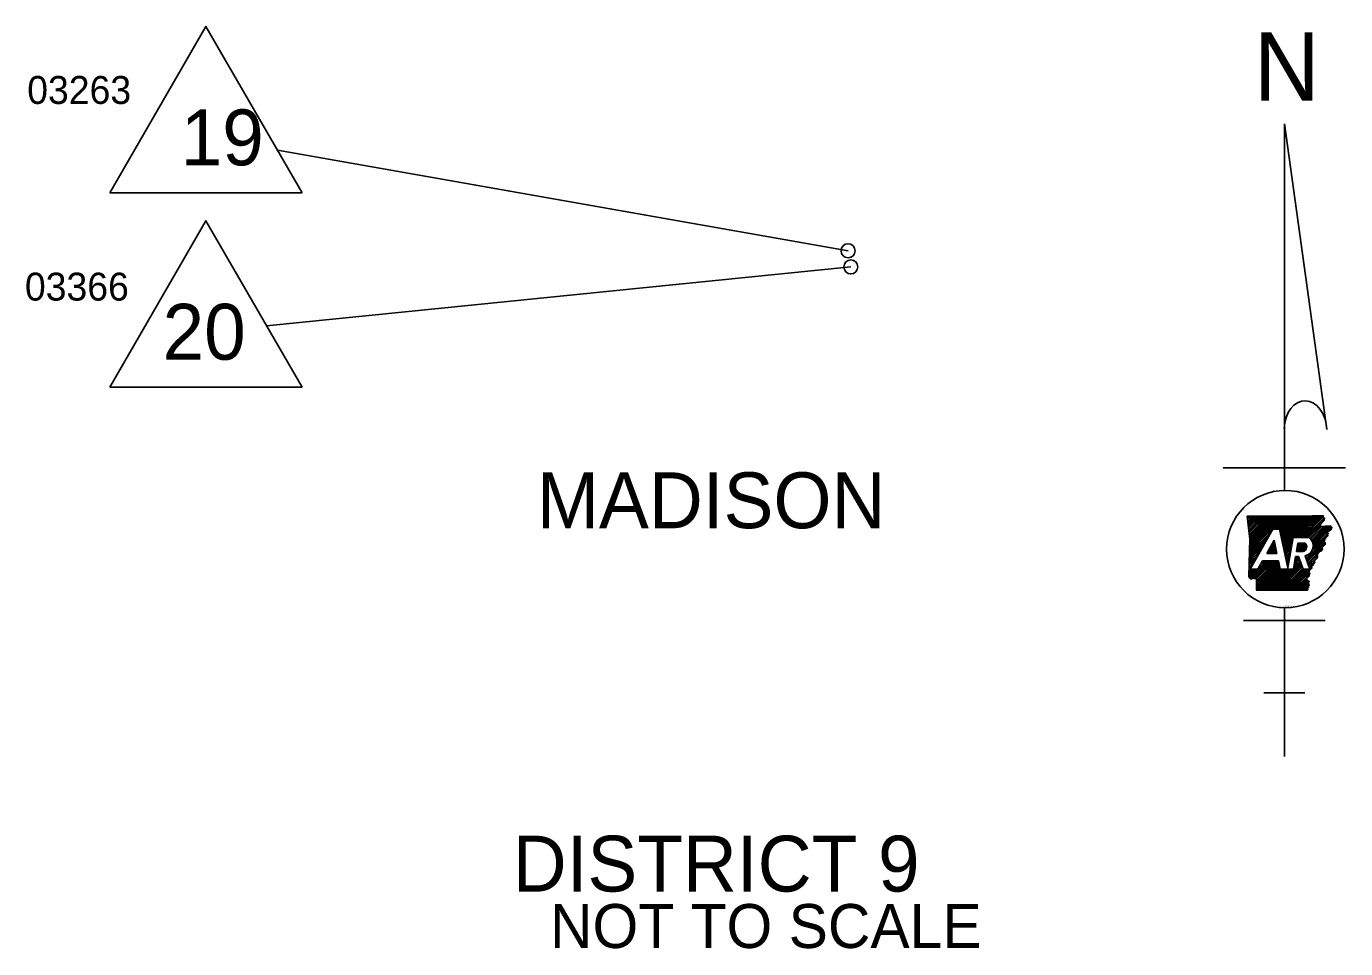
# Model space of a CAD drawing. Extents: x -24122 to 24238, y -8840 to 11381.
# Drawn here: x 11486 to 17152, y -2987 to 976 of the extents above; entities that cross this region are included whole.
import ezdxf

# ---------------------------------------------------------------- set-up
doc = ezdxf.new("R2010")
doc.units = 0
for name, color, linetype in [('R_Annotation', 7, 'Continuous'), ('R_Border', 7, 'Continuous'), ('R_No Plot', 7, 'Continuous')]:
    doc.layers.add(name, color=color, linetype=linetype)

msp = doc.modelspace()

# ---------------------------------------------------------------- linework, layer by layer
at = {"layer": 'R_Annotation'}
for p, q in [((16888.7, 557.8), (17070.5, -756.3)), ((16888.7, -1018.1), (16888.7, 557.8)), ((15014.9, 12.1), (12564.2, 445)), ((11844.1, 260.6), (12670.7, 260.6)), ((15026.9, -57.3), (12517.8, -310)), ((11844.1, -574.8), (12670.7, -574.8)), ((16625.5, -920.6), (17151.8, -920.6)), ((16729, -1131), (16731.2, -1128.8)), ((16729.8, -1137.1), (16738.1, -1128.8)), ((16730.6, -1143.3), (16745.1, -1128.8)), ((16731.3, -1149.5), (16752.1, -1128.8)), ((16732.1, -1155.7), (16759, -1128.8)), ((16732.9, -1161.9), (16766, -1128.8)), ((16733.6, -1168.1), (16773, -1128.8)), ((16734.4, -1174.3), (16779.9, -1128.8)), ((16735.2, -1180.5), (16786.9, -1128.8)), ((16736, -1186.7), (16793.8, -1128.8)), ((16736.7, -1192.9), (16800.8, -1128.8)), ((16737.5, -1199.1), (16807.8, -1128.8)), ((16738.3, -1205.3), (16814.7, -1128.8)), ((16739, -1211.5), (16821.7, -1128.8)), ((16739.3, -1280.9), (16891.5, -1128.7)), ((16739.5, -1273.7), (16884.5, -1128.7)), ((16739.7, -1266.5), (16877.5, -1128.7)), ((16739.8, -1217.7), (16828.7, -1128.8)), ((16740, -1259.3), (16870.5, -1128.7)), ((16740.2, -1252.1), (16863.6, -1128.8)), ((16740.5, -1244.9), (16856.6, -1128.8)), ((16740.6, -1223.9), (16835.6, -1128.8)), ((16740.7, -1237.7), (16849.6, -1128.8)), ((16740.9, -1230.5), (16842.6, -1128.8)), ((16842.7, -1184.4), (16898.5, -1128.7)), ((16849.7, -1184.4), (16905.4, -1128.7)), ((16856.6, -1184.4), (16912.5, -1128.6)), ((16863.6, -1184.4), (16919.5, -1128.5)), ((16867.9, -1187.1), (16926.6, -1128.4)), ((16869.2, -1192.8), (16933.7, -1128.3)), ((16870.4, -1198.5), (16940.8, -1128.2)), ((16871.6, -1204.3), (16947.8, -1128.1)), ((16872.9, -1210), (16954.9, -1128)), ((16874.1, -1215.7), (16962, -1127.8)), ((16875.3, -1221.5), (16969.1, -1127.7)), ((16876.5, -1227.2), (16976.1, -1127.6)), ((16877.8, -1233), (16983.2, -1127.5)), ((16879, -1238.7), (16990.3, -1127.4)), ((16880.2, -1244.4), (16997.4, -1127.3)), ((16881.5, -1250.2), (17004.4, -1127.2)), ((16882.7, -1255.9), (17011.5, -1127)), ((16883.9, -1261.6), (17018.7, -1126.9)), ((16932.3, -1220.2), (17025.8, -1126.7)), ((16939.3, -1220.2), (17032.9, -1126.6)), ((16946.2, -1220.2), (17040.1, -1126.4)), ((16953.2, -1220.2), (17047.2, -1126.2)), ((16960.2, -1220.2), (17054.3, -1126.1)), ((16967.1, -1220.2), (17055.9, -1131.5)), ((16741.3, -1356), (16838.5, -1184.4)), ((16838.5, -1184.4), (16867.4, -1184.4)), ((16974.1, -1220.2), (17059.3, -1135.1)), ((16981.1, -1220.2), (17060.2, -1141.1)), ((16988, -1220.2), (17044.2, -1164)), ((16994.4, -1220.9), (17042.9, -1172.3)), ((16998.2, -1224), (17050.2, -1172)), ((17001.6, -1227.6), (17057.6, -1171.6)), ((17004.6, -1231.5), (17064.9, -1171.2)), ((17007.2, -1235.9), (17072.2, -1170.8)), ((17009.3, -1240.8), (17079.6, -1170.5)), ((17010.9, -1246.1), (17086.2, -1170.8)), ((17011.8, -1252.1), (17089.5, -1174.5)), ((17086.4, -1184.6), (17092.7, -1178.2)), ((16738.3, -1309.7), (16805.7, -1242.3)), ((16738.6, -1302.5), (16814.8, -1226.2)), ((16738.8, -1295.3), (16823.9, -1210.2)), ((16739, -1288.1), (16833, -1194.1)), ((16812.8, -1288.7), (16844.6, -1232.5)), ((16830.6, -1257.3), (16846.5, -1241.4)), ((16839.7, -1241.3), (16845.3, -1235.7)), ((16885.1, -1267.4), (16924.7, -1227.9)), ((16886.4, -1273.1), (16923.2, -1236.3)), ((16887.6, -1278.9), (16921.7, -1244.7)), ((16926, -1220.2), (16993.5, -1220.2)), ((16940.7, -1281.1), (16977.3, -1244.4)), ((16942.1, -1272.7), (16970.4, -1244.4)), ((16943.6, -1264.3), (16963.4, -1244.4)), ((16945, -1255.8), (16956.4, -1244.4)), ((16946.5, -1247.4), (16949.5, -1244.4)), ((16947, -1244.4), (16978.7, -1244.4)), ((16981.7, -1310.2), (17058.9, -1233)), ((16983.5, -1315.3), (17060.2, -1238.6)), ((16985.4, -1320.4), (17061.5, -1244.3)), ((17004.4, -1280.5), (17057.6, -1227.3)), ((17010.4, -1267.5), (17073.6, -1204.3)), ((17011.9, -1259.1), (17072.8, -1198.1)), ((17065.8, -1219), (17074.4, -1210.4)), ((16737.6, -1331.3), (16778.5, -1290.5)), ((16737.8, -1324.1), (16787.6, -1274.4)), ((16738.1, -1316.9), (16796.7, -1258.3)), ((16812.8, -1288.7), (16856.6, -1288.7)), ((16813.2, -1288.7), (16849, -1252.9)), ((16820.1, -1288.7), (16850.2, -1258.6)), ((16821.5, -1273.4), (16847.7, -1247.1)), ((16827.1, -1288.7), (16851.4, -1264.4)), ((16834.1, -1288.7), (16852.6, -1270.1)), ((16841, -1288.7), (16853.9, -1275.8)), ((16848, -1288.7), (16855.1, -1281.6)), ((16855, -1288.7), (16856.3, -1287.3)), ((16888.8, -1284.6), (16920.3, -1253.2)), ((16890.1, -1290.3), (16918.8, -1261.6)), ((16891.3, -1296.1), (16917.3, -1270)), ((16892.5, -1301.8), (16915.8, -1278.5)), ((16893.7, -1307.5), (16914.4, -1286.9)), ((16895, -1313.3), (16912.9, -1295.3)), ((16934.7, -1315.4), (16948.6, -1301.5)), ((16936.1, -1306.9), (16941.6, -1301.5)), ((16948.8, -1301.5), (16937.1, -1301.5)), ((16940.6, -1281.1), (16969.6, -1281.1)), ((16947.6, -1281.1), (16981.2, -1247.5)), ((16969, -1356), (16948.8, -1301.5)), ((16954.6, -1281.1), (16983.6, -1252.2)), ((16961.6, -1281.1), (16984.8, -1257.8)), ((16968.5, -1281.1), (16984.3, -1265.4)), ((16977.4, -1298.5), (16998.6, -1356)), ((16977.9, -1300), (16980, -1297.9)), ((16979.8, -1305.1), (16993, -1291.8)), ((16987.3, -1325.4), (17062.8, -1250)), ((16989.2, -1330.5), (17031, -1288.7)), ((16991, -1335.6), (17030.2, -1296.5)), ((17039, -1280.7), (17048.7, -1271)), ((16735.8, -1388.9), (16768.6, -1356)), ((16735.9, -1381.8), (16761.7, -1356)), ((16736.2, -1374.6), (16754.7, -1356)), ((16736.4, -1367.4), (16747.7, -1356)), ((16736.6, -1360.2), (16742.1, -1354.7)), ((16736.9, -1352.9), (16751.2, -1338.6)), ((16737.1, -1345.7), (16760.3, -1322.6)), ((16737.4, -1338.5), (16769.4, -1306.5)), ((16738.4, -1393.2), (16811.6, -1320)), ((16774.7, -1356), (16741.3, -1356)), ((16742.5, -1396.1), (16818.6, -1320)), ((16747.5, -1398), (16825.5, -1320)), ((16755.8, -1396.7), (16832.5, -1320)), ((16762.9, -1396.6), (16839.5, -1320)), ((16768.3, -1398.1), (16846.4, -1320)), ((16768.6, -1411.8), (16860.4, -1320)), ((16768.6, -1404.8), (16853.4, -1320)), ((16768.6, -1418.7), (16864, -1323.3)), ((16768.6, -1425.7), (16865.3, -1329.1)), ((16768.6, -1432.6), (16866.5, -1334.8)), ((16768.7, -1439.6), (16867.7, -1340.5)), ((16768.8, -1446.4), (16868.9, -1346.3)), ((16795.1, -1320), (16774.7, -1356)), ((16775.7, -1446.4), (16870.2, -1352)), ((16782.6, -1342.1), (16804.6, -1320)), ((16782.7, -1446.5), (16873.1, -1356)), ((16789.6, -1446.5), (16880.1, -1356)), ((16791.7, -1326), (16797.7, -1320)), ((16863.3, -1320), (16795.1, -1320)), ((16796.6, -1446.5), (16887, -1356)), ((16803.5, -1446.5), (16894, -1356)), ((16810.5, -1446.5), (16901, -1356)), ((16817.5, -1446.5), (16907.9, -1356)), ((16824.4, -1446.5), (16914.9, -1356)), ((16831.4, -1446.5), (16921.9, -1356)), ((16838.3, -1446.5), (16958.1, -1326.7)), ((16845.3, -1446.6), (16960, -1331.8)), ((16852.2, -1446.6), (16961.9, -1336.9)), ((16859.2, -1446.6), (16963.8, -1342)), ((16866.1, -1446.6), (16965.6, -1347.1)), ((16927.6, -1356), (16871, -1356)), ((16873.1, -1446.6), (16967.5, -1352.2)), ((16880, -1446.6), (16970.6, -1356)), ((16887, -1446.6), (16977.6, -1356)), ((16894, -1446.6), (16984.6, -1356)), ((16896.2, -1319), (16911.4, -1303.8)), ((16897.4, -1324.8), (16910, -1312.2)), ((16898.6, -1330.5), (16908.5, -1320.7)), ((16899.9, -1336.2), (16907, -1329.1)), ((16900.9, -1446.7), (16991.5, -1356)), ((16901.1, -1342), (16905.6, -1337.5)), ((16902.3, -1347.7), (16904.1, -1346)), ((16928.8, -1349.1), (16956.3, -1321.7)), ((16930.3, -1340.7), (16954.4, -1316.6)), ((16931.7, -1332.2), (16952.5, -1311.5)), ((16933.2, -1323.8), (16950.6, -1306.4)), ((16998.6, -1356), (16969, -1356)), ((16992.9, -1340.7), (17029.4, -1304.2)), ((16994.8, -1345.8), (17016.2, -1324.4)), ((16996.7, -1350.9), (17013.2, -1334.4)), ((16907.9, -1446.7), (16993.9, -1360.7)), ((16914.8, -1446.7), (16994.2, -1367.3)), ((16921.8, -1446.7), (16994.5, -1374)), ((16928.7, -1446.7), (16994.8, -1380.6)), ((16935.7, -1446.7), (16983.4, -1399)), ((16942.6, -1446.7), (16985.5, -1403.8)), ((16949.6, -1446.7), (16987.7, -1408.7)), ((16956.5, -1446.7), (16989.8, -1413.5)), ((16963.5, -1446.8), (16992, -1418.3)), ((16970.5, -1446.8), (16993.8, -1423.5)), ((16977.4, -1446.8), (16990.6, -1433.6)), ((16984.4, -1446.8), (16987.5, -1443.7)), ((16888.7, -2161.8), (16888.7, -1522.2)), ((16713.2, -1576.5), (17064.1, -1576.5)), ((16800.9, -1888.1), (16976.4, -1888.1))]:
    msp.add_line(p, q, dxfattribs=at)
for points in [[(12670.7, 260.6), (12257.4, 976.4), (11844.1, 260.6)], [(12670.7, -574.8), (12257.4, 141), (11844.1, -574.8)], [(16728.7, -1128.8), (16824.8, -1128.8), (16909.2, -1128.7), (17008.7, -1127.1), (17054.8, -1126)], [(16728.7, -1128.8), (16824.8, -1128.8), (16909.2, -1128.7), (17008.7, -1127.1), (17054.8, -1126)], [(16739.4, -1278.2), (16741, -1227.5), (16728.7, -1128.8)], [(16735.7, -1388.8), (16741, -1227.6), (16728.7, -1128.8)], [(16867.4, -1184.4), (16903.1, -1351.4), (16926, -1220.2)], [(17085, -1170.2), (17093.3, -1178.9), (17072.6, -1195.9), (17074.8, -1213.1), (17057, -1224.9), (17063.1, -1251.3), (17049.4, -1263.8), (17048.2, -1277.4), (17031.5, -1283.4), (17028.9, -1309.1), (17016.9, -1321.9), (17011.1, -1341.2), (16993.7, -1357.2), (16995, -1385.3), (16983.2, -1398.6), (16994, -1422.8), (16986.5, -1446.8)], [(17040.5, -1172.5), (17085.6, -1170.1)], [(17040.5, -1172.4), (17085.6, -1170.2)], [(16844.6, -1232.5), (16856.6, -1288.7)], [(16940.6, -1281.1), (16947, -1244.4)], [(16735.7, -1388.8), (16739.4, -1278.2)], [(16937.1, -1301.5), (16927.6, -1356)], [(16871, -1356), (16863.3, -1320)], [(16986.5, -1446.8), (16768.7, -1446.4), (16768.6, -1398.3)], [(16986.5, -1446.8), (16768.7, -1446.4), (16768.6, -1398.4)]]:
    msp.add_lwpolyline(points, dxfattribs=at)
for centre in [(15014.9, 12.1), (15026.9, -57.3)]:
    msp.add_circle(centre, 30.2, dxfattribs=at)
for centre, major_axis, ratio, start_param, end_param in [((16979.5, -759.2), (-3.9, 126.3), 0.719778, 4.712385, 7.768526), ((16962.6, -1259.9), (-22.3, 0), 0.999987, 1.887169, 3.90762), ((16968.4, -1255.9), (-43.6, 0), 0.999987, 1.777838, 4.099264)]:
    msp.add_ellipse(centre, major_axis=major_axis, ratio=ratio, start_param=start_param, end_param=end_param, dxfattribs=at)
msp.add_ellipse((16892.8, -1270.1), major_axis=(252.1, 0), ratio=0.999976, dxfattribs=at)
for points in [[(17054.8, -1126), (17055.1, -1128.7), (17055.9, -1130), (17056, -1132.5), (17057, -1133.6), (17058.8, -1134.7), (17060.3, -1136.4), (17060.7, -1138.4), (17060.2, -1140.5), (17060.1, -1142.8), (17059.8, -1144.9), (17059.4, -1146.7), (17058, -1148.2), (17056.7, -1149.2), (17055.4, -1150.4), (17054.5, -1151.8), (17053, -1153.2), (17051.4, -1154.7), (17050.2, -1156), (17048.9, -1157.7), (17048.3, -1159.5), (17047, -1160.8), (17045.9, -1162), (17044.5, -1163.6), (17043.8, -1165.2), (17042.4, -1167), (17042.1, -1168.8), (17041.2, -1170.2), (17041.2, -1170.5)], [(17054.8, -1126), (17055.1, -1128.7), (17055.9, -1130), (17056, -1132.5), (17057, -1133.6), (17058.8, -1134.7), (17060.3, -1136.4), (17060.7, -1138.4), (17060.2, -1140.5), (17060.1, -1142.8), (17059.8, -1144.8), (17059.5, -1146.7), (17058, -1148.2), (17056.7, -1149.2), (17055.4, -1150.5), (17054.5, -1151.8), (17053, -1153.2), (17051.4, -1154.7), (17050.2, -1156), (17049, -1157.7), (17048.4, -1159.5), (17047, -1160.8), (17045.9, -1162), (17044.5, -1163.6), (17043.8, -1165.2), (17042.4, -1167.1), (17042.1, -1168.8), (17041.2, -1170.3), (17041.2, -1170.5)], [(17085, -1170.2), (17085.6, -1170.2), (17087.6, -1172.3), (17088.5, -1174.1), (17089.9, -1175.1), (17091.3, -1175.6), (17092.5, -1177), (17093.2, -1178.5), (17092.8, -1179.8), (17091.1, -1179.9), (17089.3, -1180.2), (17087.5, -1180.1), (17086.1, -1181.4), (17087.4, -1182.9), (17089.1, -1184.4), (17089.6, -1186), (17088.6, -1187.5), (17086.7, -1188.4), (17084.9, -1189.1), (17083.2, -1190.5), (17082.4, -1191.9), (17080.6, -1192.5), (17078.7, -1193), (17077.1, -1193.2), (17075.2, -1193.6), (17073.3, -1194.5), (17072.6, -1196), (17072.8, -1198.2), (17072.7, -1200.5), (17074.7, -1201.3), (17076.4, -1201.4), (17078.1, -1202.2), (17077.9, -1203.5), (17076.6, -1205.2), (17075.2, -1206.5), (17073.7, -1207.2), (17072.3, -1208.4), (17072.8, -1209.7), (17074, -1210.5), (17074.9, -1211.9), (17074.8, -1213.1), (17073.4, -1214), (17071.8, -1213.6), (17070.7, -1212.1), (17069.4, -1211.7), (17068.2, -1211.2), (17067, -1211.9), (17067, -1213.6), (17066.5, -1215.5), (17066.9, -1216.8), (17067.4, -1218.7), (17067.3, -1220.2), (17066.9, -1222.2), (17065.9, -1224.3), (17064.7, -1224.9), (17064.2, -1222.7), (17064, -1220.8), (17063.2, -1219.8), (17062.3, -1219.7), (17061.1, -1220.6), (17059.7, -1222), (17058, -1223.5), (17057, -1224.9), (17057.5, -1226.8), (17058.8, -1227.2), (17059.8, -1226.9), (17060.4, -1225.7), (17061.3, -1225.6), (17062.3, -1227.4)], [(17062.3, -1227.4), (17062.6, -1229.1), (17061.6, -1230.9), (17061.2, -1232.8), (17061.3, -1234.6), (17059.4, -1235.6), (17057.8, -1236.8), (17058.8, -1238.3), (17060.6, -1239.6), (17062.3, -1240.5), (17063.4, -1241.6), (17063.7, -1244), (17064, -1245.6), (17064.7, -1247.7), (17064.9, -1249.2), (17063.8, -1251), (17062.6, -1251.3), (17061.2, -1250.9), (17059.7, -1250.8), (17058.5, -1251.9), (17057.6, -1253.6), (17056.7, -1255.3), (17056, -1256.7), (17055.3, -1258.3), (17054.1, -1260.1), (17052.5, -1260.3), (17050.6, -1260.8), (17049.4, -1262.1), (17049.6, -1264.3), (17050.7, -1265.8), (17051.5, -1267.6), (17052.1, -1269.3), (17051.8, -1271.3), (17051, -1272.8), (17049.9, -1273.7), (17049.4, -1275.6), (17048.6, -1277), (17047.9, -1277.5), (17046.5, -1277.4), (17045, -1277.1), (17043.7, -1277.2), (17042.4, -1277.8), (17041.2, -1277.4), (17039.9, -1276), (17038.8, -1274.9), (17037.6, -1274.5), (17036.3, -1275.2), (17036.1, -1277.1), (17036.7, -1279.1), (17037.2, -1281.9), (17036.7, -1283.5), (17036.5, -1286.3)], [(17036.5, -1286.3), (17034.5, -1287.9), (17033.5, -1289.5), (17028.2, -1289), (17028.4, -1290.9), (17026.5, -1291.9), (17024.8, -1293.1), (17025.8, -1294.5), (17027.6, -1295.8), (17029.4, -1296.8), (17030.5, -1297.8), (17030.8, -1300.3), (17031.1, -1301.8), (17031.7, -1304), (17031.9, -1305.4), (17030.8, -1307.2), (17029.6, -1307.6), (17028.3, -1307.1), (17026.7, -1307), (17025.5, -1308.2), (17024.6, -1309.9), (17023.7, -1311.6), (17023, -1313), (17022.3, -1314.5), (17021.1, -1316.3), (17019.5, -1316.6), (17017.6, -1317.1), (17016.5, -1318.4), (17016.6, -1320.6), (17017.7, -1322.1), (17018.5, -1323.9), (17019.1, -1325.5), (17018.9, -1327.5), (17018, -1329), (17016.9, -1329.9), (17016.5, -1331.8), (17015.7, -1333.3), (17015, -1333.7), (17013.6, -1333.6), (17012, -1333.3), (17010.7, -1333.4), (17009.5, -1334.1), (17008.2, -1333.6), (17006.9, -1332.2), (17005.8, -1331.2), (17004.6, -1330.7), (17003.4, -1331.4), (17003.2, -1333.4), (17003.8, -1335.4), (17004.3, -1338.1), (17003.8, -1339.8), (17003.6, -1342.5)], [(17003.6, -1342.5), (17003.4, -1342.6), (17002.4, -1344), (17003, -1346.1), (17005.3, -1346.9), (17006.3, -1348.9), (17006.4, -1350.7), (17005.6, -1353.1), (17004.6, -1354.3), (17002.5, -1354.7), (17000.9, -1355), (17000.7, -1357.8), (16999.9, -1359.1), (16998.7, -1359.5), (16996.9, -1358.7), (16995.8, -1358.2), (16994.5, -1357.6), (16992.8, -1356.7), (16991.6, -1356.8), (16991.9, -1359.4), (16992.1, -1359.5), (16993.5, -1361.5), (16994.9, -1363.1), (16995.6, -1364.9)], [(17003.6, -1342.5), (17003.4, -1342.6), (17002.4, -1344), (17003, -1346.1), (17005.3, -1346.9), (17006.3, -1348.9), (17006.4, -1350.7), (17005.6, -1353.1), (17004.6, -1354.3), (17002.5, -1354.7), (17000.9, -1355), (17000.7, -1357.8), (16999.9, -1359.1), (16998.7, -1359.5), (16996.9, -1358.7), (16995.8, -1358.2), (16994.5, -1357.6), (16992.8, -1356.7), (16991.6, -1356.8), (16991.9, -1359.4), (16992.1, -1359.5), (16993.5, -1361.5), (16994.9, -1363.1), (16995.6, -1364.9)], [(16768.6, -1398.3), (16768.8, -1398.5), (16767.7, -1397.7), (16766.1, -1396.9), (16764.4, -1396.8), (16762.2, -1396.5), (16760.3, -1396.4), (16758.5, -1395.1), (16756.5, -1396.4), (16754.2, -1397.4), (16752.9, -1396.2), (16751.2, -1397), (16750, -1396.6), (16747.9, -1398.1), (16745.9, -1397.5), (16744.5, -1397.9), (16742.7, -1397.9), (16742.4, -1395.8), (16740.6, -1395.6), (16739.1, -1394.7), (16738.1, -1392.7), (16737.4, -1391), (16735.7, -1388.8)], [(16768.6, -1398.4), (16768.8, -1398.5), (16767.7, -1397.7), (16766.1, -1396.9), (16764.4, -1396.8), (16762.2, -1396.5), (16760.4, -1396.3), (16758.5, -1395.1), (16756.4, -1396.4), (16754.2, -1397.3), (16752.9, -1396.3), (16751.1, -1397), (16750, -1396.6), (16747.9, -1398.1), (16745.9, -1397.5), (16744.5, -1397.9), (16742.7, -1397.9), (16742.3, -1395.9), (16740.6, -1395.6), (16739.1, -1394.7), (16738.1, -1392.6), (16737.4, -1391), (16735.7, -1388.8)], [(16995.6, -1364.9), (16995, -1366.3), (16994.3, -1368.6), (16994.5, -1370.6), (16995.4, -1372.4), (16996.8, -1373.3), (16998.4, -1374.7), (16998.3, -1376.8), (16997.4, -1377.5), (16995.2, -1377), (16993.7, -1376.3), (16992.3, -1376.7), (16990.5, -1377.6), (16989.1, -1377.8), (16989.2, -1380.7), (16991, -1382.7), (16992.6, -1382.7), (16994.5, -1382.9), (16995.1, -1385), (16994, -1386.8), (16992.3, -1387.7), (16990, -1386.6), (16988.4, -1385.5), (16986.8, -1384.4), (16984.8, -1383.9), (16983.6, -1384.1), (16983.1, -1386.6), (16984, -1388.9), (16985.6, -1390.5), (16987, -1392.5), (16986.8, -1394), (16985.7, -1394.4), (16983.8, -1394.8), (16982.7, -1395.4), (16982.4, -1395.8), (16983, -1397.9), (16983.5, -1400.1), (16983.5, -1401.8), (16982.9, -1403.3), (16981.8, -1405.6), (16982, -1407.2), (16982.7, -1407.9), (16983.6, -1407.7), (16984.8, -1406.9), (16985.5, -1405.9), (16986.2, -1404.7), (16987.4, -1403.7), (16989, -1404.6), (16989.3, -1406.4), (16988.4, -1408), (16987.2, -1408.8), (16985.7, -1409.4), (16984.5, -1410.6), (16984.8, -1412.2), (16985.7, -1413), (16987.9, -1412.6), (16989.4, -1411.9), (16990.3, -1411.2), (16991.2, -1410.1), (16991.8, -1409.1), (16992.6, -1408), (16993.9, -1407.7), (16994.6, -1408.6), (16994.3, -1410.6), (16993.5, -1412.6), (16992.4, -1414.2), (16991.1, -1415.3), (16989.6, -1417.7), (16989.9, -1420), (16990.5, -1421.9), (16991.3, -1423.3), (16992.7, -1423), (16994.3, -1422.8), (16995.2, -1423.5), (16995.2, -1425.2), (16994, -1426.9), (16992.8, -1428.4), (16992.3, -1430.5), (16992.5, -1432), (16992.5, -1433.3), (16992, -1434.9), (16991.2, -1435.7), (16989, -1435.7), (16986.7, -1435.4), (16985.4, -1436.1), (16985.7, -1438.1), (16987, -1439.6), (16988, -1440.4), (16989.3, -1442), (16989.9, -1443.4), (16989.8, -1444.6), (16988.9, -1445.6), (16986.5, -1446.8)], [(16995.6, -1364.9), (16995, -1366.3), (16994.3, -1368.6), (16994.5, -1370.6), (16995.4, -1372.4), (16996.8, -1373.3), (16998.4, -1374.7), (16998.3, -1376.8), (16997.4, -1377.5), (16995.2, -1377), (16993.7, -1376.3), (16992.3, -1376.7), (16990.5, -1377.6), (16989.1, -1377.8), (16989.2, -1380.7), (16991, -1382.7), (16992.6, -1382.7), (16994.5, -1382.9), (16995.1, -1385), (16994, -1386.8), (16992.3, -1387.7), (16990, -1386.6), (16988.4, -1385.5), (16986.8, -1384.4), (16984.8, -1383.9), (16983.6, -1384.1), (16983.1, -1386.6), (16984, -1388.9), (16985.6, -1390.5), (16987, -1392.5), (16986.8, -1394), (16985.7, -1394.4), (16983.8, -1394.8), (16982.7, -1395.4), (16982.4, -1395.8), (16983, -1397.9), (16983.5, -1400.1), (16983.5, -1401.8), (16982.9, -1403.3), (16981.8, -1405.6), (16982, -1407.2), (16982.7, -1407.9), (16983.6, -1407.7), (16984.8, -1406.9), (16985.5, -1405.9), (16986.2, -1404.7), (16987.4, -1403.7), (16989, -1404.6), (16989.3, -1406.4), (16988.4, -1408), (16987.2, -1408.8), (16985.7, -1409.4), (16984.5, -1410.6), (16984.8, -1412.2), (16985.7, -1413), (16987.9, -1412.6), (16989.4, -1411.9), (16990.3, -1411.2), (16991.2, -1410.1), (16991.8, -1409.1), (16992.6, -1408), (16993.9, -1407.7), (16994.6, -1408.6), (16994.3, -1410.6), (16993.5, -1412.6), (16992.4, -1414.2), (16991.1, -1415.3), (16989.6, -1417.7), (16989.9, -1420), (16990.5, -1421.9), (16991.3, -1423.3), (16992.7, -1423), (16994.3, -1422.8), (16995.2, -1423.5), (16995.2, -1425.2), (16994, -1426.9), (16992.8, -1428.4), (16992.3, -1430.5), (16992.5, -1432), (16992.5, -1433.3), (16992, -1434.9), (16991.2, -1435.7), (16989, -1435.7), (16986.7, -1435.4), (16985.4, -1436.1), (16985.7, -1438.1), (16987, -1439.6), (16988, -1440.4), (16989.3, -1442), (16989.9, -1443.4), (16989.8, -1444.6), (16988.9, -1445.6), (16986.5, -1446.8)]]:
    msp.add_spline(points, degree=3, dxfattribs=at)

# ---------------------------------------------------------------- texts
for s, height, p in [('N', 293.3, (16757.9, 657)), ('19', 240, (12148.8, 379.2)), ('20', 240, (12071.3, -456.2)), ('STS 10-03-17', 7.288, (16868.6, -1520.1)), ('DISTRICT 9', 240, (13574.8, -2742))]:
    msp.add_text(s, height=height, dxfattribs=at).set_placement(p)
at = {"layer": 'R_Border'}
for s, height, p in [('MADISON', 240, (13678, -1180.4)), ('NOT TO SCALE', 189, (13735, -2984.6))]:
    msp.add_text(s, height=height, dxfattribs=at).set_placement(p)
at = {"layer": 'R_No Plot'}
for s, p in [('03263', (11489.9, 643.1)), ('03366', (11480, -202.1))]:
    msp.add_text(s, height=120, dxfattribs=at).set_placement(p)

doc.saveas('drawing.dxf')
